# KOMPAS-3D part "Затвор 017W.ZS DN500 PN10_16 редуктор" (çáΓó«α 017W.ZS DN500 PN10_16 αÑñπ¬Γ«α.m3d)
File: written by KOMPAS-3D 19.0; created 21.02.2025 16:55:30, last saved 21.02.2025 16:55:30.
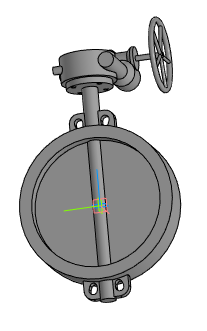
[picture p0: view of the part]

Document properties: Автор: Евгений; Полное имя файла: Затвор 017W.ZS DN500 PN10_16 редуктор.a3d

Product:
- Part/product: Затвор 017W.ZS DN500 PN10_16 редуктор
    Масса: 171.852

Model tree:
1. Операция без истории:1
